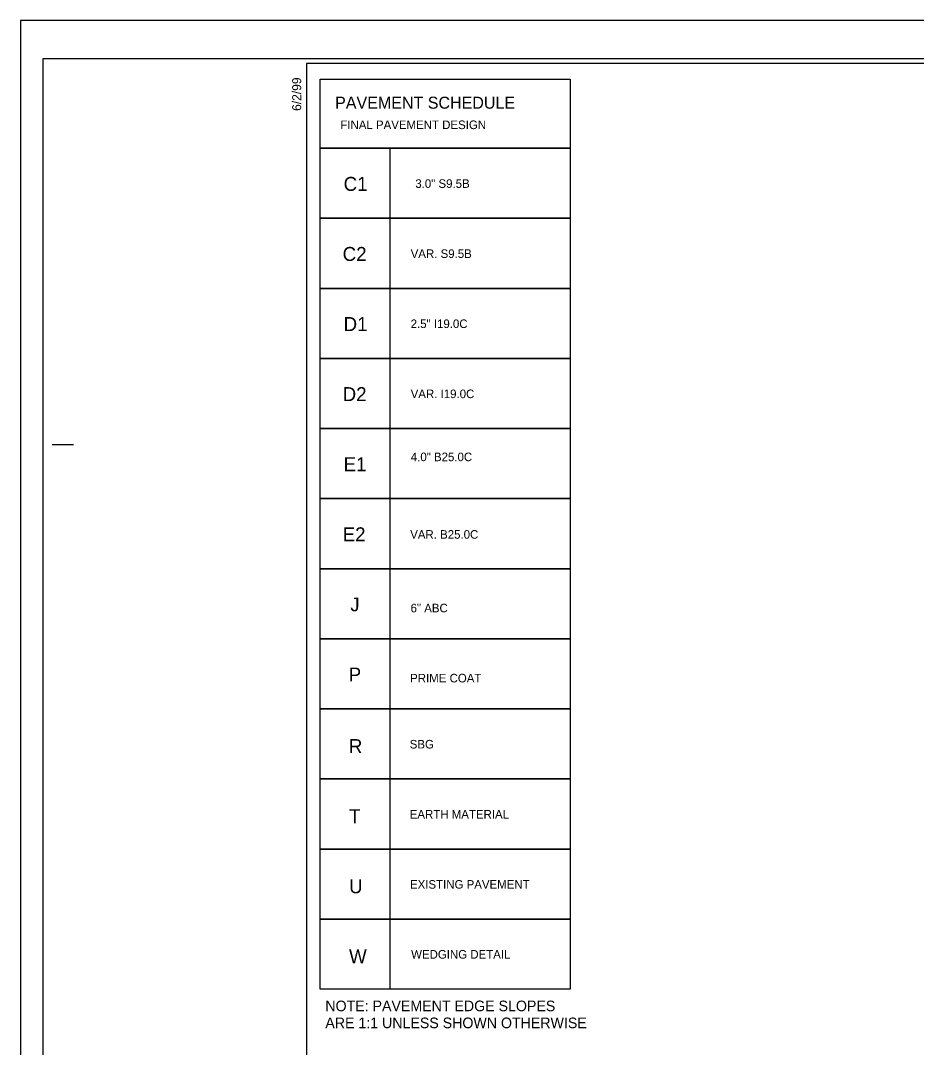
# Model space of a CAD drawing. Extents: x 1497225 to 1499181, y 579958 to 582278.
# Drawn here: x 1497225 to 1497748, y 580459 to 581058 of the extents above; entities that cross this region are included whole.
import ezdxf

# ---------------------------------------------------------------- set-up
doc = ezdxf.new("R2010")
doc.units = 0
for name, color, linetype in [('Old_Level_4', 7, 'Continuous'), ('Prop Pavement Schedule Description CELL', 7, 'Continuous'), ('Sheet Cutting Line CELL', 7, 'Continuous'), ('Sheet Plot Border Inside CELL', 7, 'Continuous'), ('Sheet Plot Border Outside CELL', 7, 'Continuous'), ('Sheet Typical CELL', 7, 'Continuous')]:
    doc.layers.add(name, color=color, linetype=linetype)

msp = doc.modelspace()

# ---------------------------------------------------------------- linework, layer by layer
at = {"layer": 'Prop Pavement Schedule Description CELL'}
msp.add_lwpolyline([(1497400.21, 581023.83), (1497546.15, 581023.83), (1497546.15, 580983.49), (1497400.21, 580983.49)], close=True, dxfattribs=at)
for points in [[(1497441.11, 580942.58), (1497400.21, 580942.58), (1497400.21, 580983.49), (1497546.15, 580983.49), (1497546.15, 580942.59), (1497441.11, 580942.59), (1497441.11, 580983.49)], [(1497441.11, 580901.67), (1497400.21, 580901.67), (1497400.21, 580942.59), (1497546.15, 580942.59), (1497546.15, 580901.67), (1497441.11, 580901.67), (1497441.11, 580942.59)], [(1497441.11, 580860.75), (1497400.21, 580860.75), (1497400.21, 580901.67), (1497546.15, 580901.67), (1497546.15, 580860.76), (1497441.11, 580860.76), (1497441.11, 580901.67)], [(1497441.11, 580819.84), (1497400.21, 580819.84), (1497400.21, 580860.76), (1497546.15, 580860.76), (1497546.15, 580819.84), (1497441.11, 580819.84), (1497441.11, 580860.76)], [(1497441.11, 580778.94), (1497400.21, 580778.94), (1497400.21, 580819.84), (1497546.15, 580819.84), (1497546.15, 580778.93), (1497441.11, 580778.93), (1497441.11, 580819.84)], [(1497441.11, 580738.02), (1497400.21, 580738.02), (1497400.21, 580778.93), (1497546.15, 580778.93), (1497546.15, 580738.02), (1497441.11, 580738.02), (1497441.11, 580778.93)], [(1497441.11, 580697.11), (1497400.21, 580697.11), (1497400.21, 580738.02), (1497546.15, 580738.02), (1497546.15, 580697.11), (1497441.11, 580697.11), (1497441.11, 580738.02)], [(1497441.11, 580656.2), (1497400.21, 580656.2), (1497400.21, 580697.11), (1497546.15, 580697.11), (1497546.15, 580656.2), (1497441.11, 580656.2), (1497441.11, 580697.11)], [(1497441.11, 580615.29), (1497400.21, 580615.29), (1497400.21, 580656.2), (1497546.15, 580656.2), (1497546.15, 580615.29), (1497441.11, 580615.29), (1497441.11, 580656.2)], [(1497441.11, 580574.39), (1497400.21, 580574.39), (1497400.21, 580615.29), (1497546.15, 580615.29), (1497546.15, 580574.39), (1497441.11, 580574.39), (1497441.11, 580615.29)], [(1497441.11, 580533.48), (1497400.21, 580533.48), (1497400.21, 580574.39), (1497546.15, 580574.39), (1497546.15, 580533.48), (1497441.11, 580533.48), (1497441.11, 580574.39)], [(1497441.11, 580492.56), (1497400.21, 580492.56), (1497400.21, 580533.48), (1497546.15, 580533.48), (1497546.15, 580492.56), (1497441.11, 580492.56), (1497441.11, 580533.47)]]:
    msp.add_lwpolyline(points, dxfattribs=at)
at = {"layer": 'Sheet Cutting Line CELL'}
for p, q in [((1498909.23, 581058.02), (1497225.23, 581058.02)), ((1497225.23, 581058.02), (1497225.23, 579958.02))]:
    msp.add_line(p, q, dxfattribs=at)
at = {"layer": 'Sheet Plot Border Inside CELL'}
msp.add_lwpolyline([(1498904.73, 581035.57), (1497238.23, 581035.57), (1497238.23, 579980.47), (1498904.73, 579980.47)], close=True, dxfattribs=at)
at = {"layer": 'Sheet Plot Border Outside CELL'}
msp.add_lwpolyline([(1498909.23, 581058.02), (1497225.23, 581058.02), (1497225.23, 579958.02), (1498909.23, 579958.02)], close=True, dxfattribs=at)
at = {"layer": 'Sheet Typical CELL'}
msp.add_line((1497243.73, 580810.52), (1497256.23, 580810.52), dxfattribs=at)
msp.add_lwpolyline([(1498892.23, 581033.02), (1497392.23, 581033.02), (1497392.23, 579983.02), (1498892.23, 579983.02)], close=True, dxfattribs=at)

# ---------------------------------------------------------------- texts
at = {"layer": 'Old_Level_4'}
for s, p in [('NOTE: PAVEMENT EDGE SLOPES ', (1497403.16, 580479.72)), ('ARE 1:1 UNLESS SHOWN OTHERWISE', (1497403.16, 580469.82))]:
    msp.add_text(s, height=6.1875, rotation=360, dxfattribs=at).set_placement(p)
at = {"layer": 'Prop Pavement Schedule Description CELL'}
for s, height, p in [('PAVEMENT SCHEDULE', 7, (1497408.87, 581006.56)), ('FINAL PAVEMENT DESIGN', 5, (1497411.93, 580994.65)), ('C1', 8.167, (1497413.84, 580958.58)), ('3.0" S9.5B', 5, (1497455.7, 580960.34)), ('C2', 8.167, (1497413.27, 580917.67)), ('VAR. S9.5B', 5, (1497452.98, 580919.43)), ('D1', 8.167, (1497413.84, 580876.75)), ('2.5" I19.0C', 5, (1497452.98, 580878.51)), ('D2', 8.167, (1497413.27, 580835.84)), ('VAR. I19.0C', 5, (1497452.98, 580837.6)), ('E1', 8.167, (1497413.84, 580794.93)), ('4.0" B25.0C', 5, (1497453.06, 580800.8)), ('E2', 8.167, (1497413.27, 580754.01)), ('VAR. B25.0C', 5, (1497452.71, 580755.53)), ('J', 8, (1497417.78, 580713.19)), ('6" ABC', 5, (1497452.94, 580712.56)), ('P', 8, (1497416.92, 580672.28)), ('PRIME COAT', 5, (1497452.67, 580671.65)), ('R', 8.17, (1497416.91, 580630.38)), ('SBG', 5, (1497452.44, 580633.08)), ('T', 8.17, (1497417.02, 580589.47)), ('EARTH MATERIAL', 5, (1497452.44, 580592.17)), ('U', 8.17, (1497417.02, 580548.56)), ('EXISTING PAVEMENT', 5, (1497452.59, 580551.26)), ('W', 8.17, (1497417.01, 580507.64)), ('WEDGING DETAIL', 5, (1497453.25, 580510.41))]:
    msp.add_text(s, height=height, dxfattribs=at).set_placement(p)
at = {"layer": 'Sheet Typical CELL'}
msp.add_text('6/2/99', height=5.25, rotation=90, dxfattribs=at).set_placement((1497389.08, 581005.27))

doc.saveas('drawing.dxf')
